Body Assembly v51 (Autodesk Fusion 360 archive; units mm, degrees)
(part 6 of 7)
sketch "Sketch1" plane through (0, 0, 0) normal (0, 0, 1) x axis (1, 0, 0)
  line L1 (-7.25, -8.75) -> (7.25, -8.75)
  line L2 (-7.25, 8.75) -> (-7.25, -8.75)
  line L3 (7.25, 8.75) -> (-7.25, 8.75)
  line L4 (7.25, -8.75) -> (7.25, 8.75)
  line L5 (-7.25, 8.75) -> (7.25, -8.75)
  line L6 (7.25, 8.75) -> (-7.25, -8.75)
  line L7 (0, 8.75) -> (0, -8.75)
  line L8 (-2.5, -2.35) -> (2.5, -2.35)
  line L9 (-2.5, 1.45) -> (-2.5, -2.35)
  line L10 (2.5, 1.45) -> (-2.5, 1.45)
  line L11 (2.5, -2.35) -> (2.5, 1.45)
  line L12 (-2.5, 1.45) -> (2.5, -2.35)
  line L13 (2.5, 1.45) -> (-2.5, -2.35)
  line L14 (7.25, -0.45) -> (-7.25, -0.45)
  line L15 (3.75, -8.75) -> (7.25, -5.25)
  line L16 (-3.75, -8.75) -> (-7.25, -5.25)
  arc A1 centre (0, 0.1797) radius 8.5703 clockwise from (-7.25, 4.75) to (7.25, 4.75)
  circle C1 centre (6, -0.45) radius 1.5
  circle C2 centre (-6, -0.45) radius 1.5
  point P6 (0, 0)
  point P1 (0, 0)
  point P7 (0, -8.75)
  point P8 (0, 8.75)
  point P13 (0, -0.45)
  point P14 (-7.25, -0.45)
  point P15 (7.25, -0.45)
  point P16 (7.25, 4.75)
  point P17 (-7.25, 4.75)
  point P19 (7.25, 4.75)
  point P18 (-7.25, 4.75)
  point P21 (7.25, -5.25)
  point P22 (3.75, -8.75)
  point P23 (7.25, -5.25)
  point P24 (3.75, -8.75)
  point P25 (-7.25, -5.25)
  point P26 (-3.75, -8.75)
  point P27 (6, -0.45)
  point P2 (7.25, -8.75)
  point P5 (7.25, 8.75)
  horizontal L1
  perpendicular L1 L2
  parallel L1 L3
  parallel L2 L4
  coincident L5 P6
  coincident L6 P6
  coincident P1 P6
  midpoint L1 P7
  midpoint L3 P8
  horizontal L8
  perpendicular L8 L9
  parallel L8 L10
  parallel L9 L11
  coincident L12 P13
  coincident L13 P13
  coincident L7 P13
  coincident L2 P14
  coincident L4 P15
  perpendicular L4 L14
  coincident P13 L14
  coincident L4 P16
  symmetric L7 P16 P17
  coincident P8 A1
  tangent L3 A1
  coincident P16 P19
  coincident P17 P18
  coincident L4 P21
  coincident L1 P22
  coincident P21 P23
  coincident P22 P24
  symmetric L7 P23 P25
  symmetric L7 P24 P26
  coincident L14 P27
  symmetric L7 C1 C2
  dimension "d1_1" distance P2 P5 = 17.5
  dimension "d2_1" distance L2 L4 = 14.5
  dimension "d3_1" distance L1 L8 = 6.4
  dimension "d4_1" distance L3 L10 = 7.3
  dimension "d5_1" distance L9 L11 = 5
  dimension "d6_1" distance P5 P16 = 4
  dimension "d7_1" distance P2 P21 = 3.5
  dimension "d8_1" distance P2 P22 = 3.5
  dimension "d9_1" diameter C1 = 3
  dimension "d10_1" distance L11 P27 = 3.5 (= "2 mm + 1.5 mm")
extrude "Extrude1" new body sketch "Sketch1" profile of L1 L2 L4 L8 L9 L10 L11 A1 L15 L16 C1 C2 against normal blind 1.7 named "d11_1"
extrude "Extrude2" new body sketch "Sketch1" profile of L8 L9 L10 L11 along normal blind 1.5 named "d13_1"
position "Position1"
position "Position2"
position "Position3"
position "Position4"
copy_paste "CutPaste2"
work_plane "WorkPlane1" AlongDistance -21
split "Split1"
combine "Combine1"
split "Split1"
remove_body "RemoveBody2"
extrude "Extrude1" add of existing geometry blind 2.2
extrude "Extrude2" add of existing geometry blind 1
extrude "Extrude3" cut of existing geometry blind -0.2
extrude "Extrude4" add of existing geometry blind 0.2
work_plane "WorkPlane2"
extrude "Extrude4" cut of existing geometry blind -0.2063 (= "( 2 mm - ( ( 1 / 16 ) * 1 in ) ) / -2")
extrude "Extrude5" cut of existing geometry blind -0.2063 (= "( 2 mm - ( ( 1 / 16 ) * 1 in ) ) / -2")
extrude "Extrude5" add of existing geometry blind 0.2063 (= "( 2 mm - ( ( 1 / 16 ) * 1 in ) ) / 2")
extrude "Extrude6" add of existing geometry blind 0.2063 (= "( 2 mm - ( ( 1 / 16 ) * 1 in ) ) / 2")
sketch "Sketch4" plane through (0, 0, 28) normal (0, 0, -1) x axis (1, 0, 0)
  line L1 (-1.6037, -23.3708) -> (-1.6037, 14.6292)
  line L2 (-0.9037, -30.2208) -> (-0.9037, -24.3248)
  line L3 (2.4963, -31.7208) -> (0.5963, -31.7208)
  line L4 (2.4963, -31.0175) -> (2.4963, -31.7208)
  line L5 (4.4963, -31.7208) -> (4.4963, -31.0175)
  line L6 (12.2963, -31.7208) -> (4.4963, -31.7208)
  line L7 (12.2963, -31.0175) -> (12.2963, -31.7208)
  line L8 (14.2963, -31.7208) -> (14.2963, -31.0175)
  line L9 (16.1963, -31.7208) -> (14.2963, -31.7208)
  line L10 (17.6963, -24.3248) -> (17.6963, -30.2208)
  line L11 (18.3963, 14.6292) -> (18.3963, -23.3708)
  line L12 (17.6963, 21.4792) -> (17.6963, 15.5831)
  line L13 (14.2963, 22.9792) -> (16.1963, 22.9792)
  line L14 (14.2963, 22.2758) -> (14.2963, 22.9792)
  line L15 (12.2963, 22.9792) -> (12.2963, 22.2758)
  line L16 (4.4963, 22.9792) -> (12.2963, 22.9792)
  line L17 (4.4963, 22.2758) -> (4.4963, 22.9792)
  line L18 (2.4963, 22.9792) -> (2.4963, 22.2758)
  line L19 (0.5963, 22.9792) -> (2.4963, 22.9792)
  line L20 (-0.9037, 15.5831) -> (-0.9037, 21.4792)
  line L21 (15.3963, 15.6292) -> (1.3963, 15.6292)
  line L22 (1.3963, 15.6292) -> (15.3963, 15.6292)
  line L23 (8.3963, -2.0612) -> (8.3963, 15.6292)
  line L24 (22.9806, 14.6292) -> (-3.2785, 14.6292)
  arc A1 centre (-0.6037, 14.6292) radius 1 clockwise from (-1.6037, 14.6292) to (-0.9037, 15.5831)
  arc A2 centre (-0.6037, -23.3708) radius 1 clockwise from (-0.9037, -24.3248) to (-1.6037, -23.3708)
  arc A3 centre (0.5963, -30.2208) radius 1.5 clockwise from (0.5963, -31.7208) to (-0.9037, -30.2208)
  arc A4 centre (3.4963, -29.1708) radius 2.1 clockwise from (2.4963, -31.0175) to (4.4963, -31.0175)
  arc A5 centre (13.2963, -29.1708) radius 2.1 clockwise from (12.2963, -31.0175) to (14.2963, -31.0175)
  arc A6 centre (16.1963, -30.2208) radius 1.5 clockwise from (17.6963, -30.2208) to (16.1963, -31.7208)
  arc A7 centre (17.3963, -23.3708) radius 1 clockwise from (18.3963, -23.3708) to (17.6963, -24.3248)
  arc A8 centre (17.3963, 14.6292) radius 1 clockwise from (17.6963, 15.5831) to (18.3963, 14.6292)
  arc A9 centre (16.1963, 21.4792) radius 1.5 clockwise from (16.1963, 22.9792) to (17.6963, 21.4792)
  arc A10 centre (13.2963, 20.4292) radius 2.1 clockwise from (14.2963, 22.2758) to (12.2963, 22.2758)
  arc A11 centre (3.4963, 20.4292) radius 2.1 clockwise from (4.4963, 22.2758) to (2.4963, 22.2758)
  arc A12 centre (0.5963, 21.4792) radius 1.5 clockwise from (-0.9037, 21.4792) to (0.5963, 22.9792)
  circle C1 centre (8.3963, 6.1292) radius 8.5
  point P48 (8.3963, 15.6292)
  point P50 (8.3963, 6.1292)
  midpoint L21 P48
  perpendicular L21 L23
  coincident L23 P50
  perpendicular L1 L24
  tangent C1 L24
  dimension "d32" diameter C1 = 17
  dimension "d33" distance L22 L24 = 1
extrude "Extrude4" new body sketch "Sketch4" profile of C1 along normal blind 27.9908
extrude "Extrude5" add of existing geometry blind 0.5092 (= "41.5 mm - 1.6138110236220502 in")
copy_paste_bodies "CutPasteBodies1"
sketch "Sketch5" plane through (0, 0, 28) normal (0, 0, -1) x axis (1, 0, 0)
  line L1 (-1.6037, -23.3708) -> (-1.6037, 14.6292)
  line L2 (-0.9037, -30.2208) -> (-0.9037, -24.3248)
  line L3 (2.4963, -31.7208) -> (0.5963, -31.7208)
  line L4 (2.4963, -31.0175) -> (2.4963, -31.7208)
  line L5 (4.4963, -31.7208) -> (4.4963, -31.0175)
  line L6 (12.2963, -31.7208) -> (4.4963, -31.7208)
  line L7 (12.2963, -31.0175) -> (12.2963, -31.7208)
  line L8 (14.2963, -31.7208) -> (14.2963, -31.0175)
  line L9 (16.1963, -31.7208) -> (14.2963, -31.7208)
  line L10 (17.6963, -24.3248) -> (17.6963, -30.2208)
  line L11 (18.3963, 14.6292) -> (18.3963, -23.3708)
  line L12 (17.6963, 21.4792) -> (17.6963, 15.5831)
  line L13 (14.2963, 22.9792) -> (16.1963, 22.9792)
  line L14 (14.2963, 22.2758) -> (14.2963, 22.9792)
  line L15 (12.2963, 22.9792) -> (12.2963, 22.2758)
  line L16 (4.4963, 22.9792) -> (12.2963, 22.9792)
  line L17 (4.4963, 22.2758) -> (4.4963, 22.9792)
  line L18 (2.4963, 22.9792) -> (2.4963, 22.2758)
  line L19 (0.5963, 22.9792) -> (2.4963, 22.9792)
  line L20 (-0.9037, 15.5831) -> (-0.9037, 21.4792)
  arc A1 centre (-0.6037, 14.6292) radius 1 clockwise from (-1.6037, 14.6292) to (-0.9037, 15.5831)
  arc A2 centre (-0.6037, -23.3708) radius 1 clockwise from (-0.9037, -24.3248) to (-1.6037, -23.3708)
  arc A3 centre (0.5963, -30.2208) radius 1.5 clockwise from (0.5963, -31.7208) to (-0.9037, -30.2208)
  arc A4 centre (3.4963, -29.1708) radius 2.1 clockwise from (2.4963, -31.0175) to (4.4963, -31.0175)
  arc A5 centre (13.2963, -29.1708) radius 2.1 clockwise from (12.2963, -31.0175) to (14.2963, -31.0175)
  arc A6 centre (16.1963, -30.2208) radius 1.5 clockwise from (17.6963, -30.2208) to (16.1963, -31.7208)
  arc A7 centre (17.3963, -23.3708) radius 1 clockwise from (18.3963, -23.3708) to (17.6963, -24.3248)
  arc A8 centre (17.3963, 14.6292) radius 1 clockwise from (17.6963, 15.5831) to (18.3963, 14.6292)
  arc A9 centre (16.1963, 21.4792) radius 1.5 clockwise from (16.1963, 22.9792) to (17.6963, 21.4792)
  arc A10 centre (13.2963, 20.4292) radius 2.1 clockwise from (14.2963, 22.2758) to (12.2963, 22.2758)
  arc A11 centre (3.4963, 20.4292) radius 2.1 clockwise from (4.4963, 22.2758) to (2.4963, 22.2758)
  arc A12 centre (0.5963, 21.4792) radius 1.5 clockwise from (-0.9037, 21.4792) to (0.5963, 22.9792)
split "Split1"
remove_body "RemoveBody1"
delete_face "DeleteFace1"
delete_face "DeleteFace2"
sketch "Sketch6" plane through (0, 0, 28) normal (0, 0, -1) x axis (1, 0, 0)
  line L1 (-0.9037, -24.3248) -> (17.6963, 15.5831)
  line L2 (-0.9037, 15.5831) -> (17.6963, -24.3248)
  line L3 (-0.8337, -23.6158) -> (17.6263, -23.6158)
  line L4 (-0.8337, 14.8742) -> (-0.8337, -23.6158)
  line L5 (17.6263, 14.8742) -> (-0.8337, 14.8742)
  line L6 (17.6263, -23.6158) -> (17.6263, 14.8742)
  line L7 (-0.8337, 14.8742) -> (17.6263, -23.6158)
  line L8 (17.6263, 14.8742) -> (-0.8337, -23.6158)
  line L9 (-4.0087, 18.0492) -> (-4.0087, -26.7908)
  line L10 (20.8013, 18.0492) -> (-4.0087, 18.0492)
  line L11 (20.8013, -26.7908) -> (20.8013, 18.0492)
  line L12 (-4.0087, -26.7908) -> (20.8013, -26.7908)
  point P2 (17.6963, 15.5831)
  point P6 (17.6963, 15.5831)
  point P4 (-0.9037, -24.3248)
  point P7 (-0.9037, -24.3248)
  point P3 (17.6963, -24.3248)
  point P8 (17.6963, -24.3248)
  point P5 (-0.9037, 15.5831)
  point P9 (-0.9037, 15.5831)
  point P10 (8.3963, -4.3708)
  point P15 (8.3963, -4.3708)
  point P13 (-0.8337, 14.8742)
  point P14 (17.6263, 14.8742)
  point P11 (17.6263, -23.6158)
  coincident P2 P6
  coincident P4 P7
  coincident P3 P8
  coincident P5 P9
  midpoint L1 P10
  horizontal L3
  perpendicular L3 L4
  parallel L3 L5
  parallel L4 L6
  coincident L7 P15
  coincident L8 P15
  coincident P10 P15
  dimension "d38" distance P13 P14 = 18.46
  dimension "d39" distance P11 P14 = 38.49
  dimension "d44" = -3.175 (= "( -1 / 8 ) * 1 in")
split "Split2"
split "Split3"
delete_face "DeleteFace3"
extrude "Extrude1" cut of existing geometry blind -33.02
delete_face "DeleteFace4"
extrude "Extrude2" cut of existing geometry blind -29.21
extrude "Extrude6" new body sketch "Sketch6" profile of L3 L4 L5 L6 L9 L12 L10 L11 along normal blind 28.4988
work_plane "WorkPlane3" AlongDistance -1.6
split "Split2"
sketch "Sketch7" plane through (0, 0, 26.4) normal (0, 0, 1) x axis (-1, 0, 0)
  line L1 (0.8337, -23.6158) -> (0.8337, 14.8742)
  line L2 (-17.6263, -23.6158) -> (0.8337, -23.6158)
  line L3 (-17.6263, 14.8742) -> (-17.6263, -23.6158)
  line L4 (0.8337, 14.8742) -> (-17.6263, 14.8742)
  line L5 (4.0087, -26.7908) -> (-20.8013, -26.7908)
  line L6 (4.0087, 18.0492) -> (4.0087, -26.7908)
  line L7 (-20.8013, 18.0492) -> (4.0087, 18.0492)
  line L8 (-20.8013, -26.7908) -> (-20.8013, 18.0492)
  line L9 (-20.8013, 6.1292) -> (4.0087, 6.1292)
  line L10 (-20.8013, -1.8708) -> (4.0087, -1.8708)
  circle C1 centre (-8.3963, 6.1292) radius 8.5
  circle C2 centre (-8.3963, 6.1292) radius 8.75
  point P12 (4.0087, 6.1292)
  point P13 (-20.8013, 6.1292)
  point P14 (4.0087, -1.8708)
  point P15 (-20.8013, -1.8708)
  coincident L6 P12
  coincident L8 P13
  perpendicular L8 L9
  coincident L6 P14
  coincident L8 P15
  perpendicular L8 L10
  dimension "d48" = 0.25
  dimension "d51" distance L9 L10 = 8
extrude "Extrude7" add sketch "Sketch7" profile of L1 L3 L4 C2 L10 against normal blind 26.8988
extrude "Extrude8" cut sketch "Sketch7" profile of L4 C2 against normal blind 38.1
offset_faces "OffsetFaces1" distance 0.75
fillet "Fillet3" radius 1.651
split "Split3"
remove_body "RemoveBody5"
mirror "Mirror1" mirrorStitchTolerance 0.1016
combine "Combine2"
component_from_bodies "Body->Comp1"
copy_paste_bodies "CutPasteBodies1"
mirror "Mirror1" mirrorStitchTolerance 0.1016
align "Align1"
extrude "Extrude1" add of existing geometry blind 6.35
extrude "Extrude9" new body of existing geometry blind 19.9898
copy_paste_bodies "CutPasteBodies2"
copy_paste "CutPaste3"
copy_paste_bodies "CutPasteBodies2"
sketch "Sketch8" plane through (0, 0, 19.9956) normal (0, 0, -1) x axis (1, 0, 0)
  line L1 (0.3963, -22.3708) -> (0.3963, -3.3708)
  line L2 (16.3963, -22.3708) -> (0.3963, -22.3708)
  line L3 (16.3963, -3.3708) -> (16.3963, -22.3708)
  line L4 (0.3963, -3.3708) -> (16.3963, -3.3708)
  line L5 (1.5713, -6.5458) -> (1.5713, -21.1958)
  line L6 (15.2213, -6.5458) -> (1.5713, -6.5458)
  line L7 (15.2213, -21.1958) -> (15.2213, -6.5458)
  line L8 (1.5713, -21.1958) -> (15.2213, -21.1958)
  line L9 (-4.0087, 18.0492) -> (20.8013, 18.0492)
  line L10 (-4.0087, -26.7908) -> (-4.0087, 18.0492)
  line L11 (20.8013, -26.7908) -> (-4.0087, -26.7908)
  line L12 (20.8013, 18.0492) -> (20.8013, -26.7908)
  line L13 (16.8763, -22.8658) -> (16.8763, -3.2059)
  line L14 (-0.0837, -22.8658) -> (16.8763, -22.8658)
  line L15 (-0.0837, -3.2059) -> (-0.0837, -22.8658)
  circle C1 centre (8.3963, -14.6208) radius 8
  circle C2 centre (8.3963, -14.6208) radius 8
  arc A1 centre (8.3963, 6.1292) radius 8.75 clockwise from (1.4656, 0.788) to (15.327, 0.788)
  arc A2 centre (16.6347, -0.2198) radius 1.651 clockwise from (15.93, -1.7129) to (15.327, 0.788)
  arc A3 centre (15.2253, -3.2059) radius 1.651 clockwise from (15.93, -1.7129) to (16.8763, -3.2059)
  arc A4 centre (1.5673, -3.2059) radius 1.651 clockwise from (-0.0837, -3.2059) to (0.8626, -1.7129)
  arc A5 centre (0.1579, -0.2198) radius 1.651 clockwise from (1.4656, 0.788) to (0.8626, -1.7129)
  circle C3 centre (8.3963, 6.1292) radius 8.5
  circle C4 centre (8.3963, 6.1292) radius 8.75
  dimension "d72" = 0.25
extrude "Extrude10" new body sketch "Sketch8" profile of L1 L2 L3 L4 L5 L6 L7 L8 C1 C2 A2 A3 L13 L14 L15 A4 A5 C4 along normal blind 5.0038
sketch "Sketch9" plane through (0, 0, 14.9918) normal (0, 0, -1) x axis (1, 0, 0)
  line L1 (-0.0837, -22.8658) -> (-0.0837, -3.2059)
  line L2 (16.8763, -22.8658) -> (-0.0837, -22.8658)
  line L3 (16.8763, -3.2059) -> (16.8763, -22.8658)
  circle C1 centre (8.3963, -14.6208) radius 8
  arc A1 centre (15.2253, -3.2059) radius 1.651 clockwise from (15.93, -1.7129) to (16.8763, -3.2059)
  arc A2 centre (16.6347, -0.2198) radius 1.651 clockwise from (15.93, -1.7129) to (15.327, 0.788)
  arc A3 centre (8.3963, 6.1292) radius 8.75 clockwise from (15.327, 0.788) to (1.4656, 0.788)
  arc A4 centre (0.1579, -0.2198) radius 1.651 clockwise from (1.4656, 0.788) to (0.8626, -1.7129)
  arc A5 centre (1.5673, -3.2059) radius 1.651 clockwise from (-0.0837, -3.2059) to (0.8626, -1.7129)
  arc A6 centre (8.3963, 6.1292) radius 8.75 clockwise from (15.327, 0.788) to (1.4656, 0.788)
  arc A7 centre (8.3963, 6.1292) radius 11.1625 clockwise from (17.2379, -0.6847) to (-0.4452, -0.6847)
  dimension "d73" = 2.4125 (= "0.125 in - 0.0300196850393694 in")
extrude "Extrude11" add sketch "Sketch9" profile of A1 A2 A3 A4 A5 A6 A7 along normal blind 15.4906
combine "Combine3"
delete_face "DeleteFace1"
delete_face "DeleteFace2"
fillet "Fillet1" radius 4.7625
sketch "Sketch10" plane through (0, 0, 8.3168) normal (0, 0, -1) x axis (1, 0, 0)
  circle C1 centre (8.3963, -14.6208) radius 4
  circle C2 centre (8.3963, -14.6208) radius 8
  circle C3 centre (8.3963, -14.6208) radius 9.5875
  dimension "d78" = 1.5875 (= "( 1 / 16 ) * 1 in")
extrude "Extrude7" cut sketch "Sketch10" along normal blind 15.24 and against normal blind 6.6802
extrude "Extrude8" add of existing geometry blind 0.0052 (= "2.047E-04 in")
sketch "Sketch11" plane through (0, 0, 14.9918) normal (0, 0, -1) x axis (1, 0, 0)
  line L1 (16.8763, -22.8658) -> (13.2892, -22.8658)
  line L2 (16.8763, -19.0941) -> (16.8763, -22.8658)
  line L3 (16.8763, -9.3559) -> (16.8763, -10.1476)
  line L4 (-0.0837, -10.1476) -> (-0.0837, -9.3559)
  line L5 (-0.0837, -22.8658) -> (-0.0837, -19.0941)
  line L6 (3.5034, -22.8658) -> (-0.0837, -22.8658)
  circle C1 centre (8.3963, -14.6208) radius 8
  arc A1 centre (8.3963, -14.6208) radius 9.5875 clockwise from (16.8763, -10.1476) to (16.8763, -19.0941)
  arc A2 centre (12.1138, -9.3559) radius 4.7625 clockwise from (11.0021, -4.7249) to (16.8763, -9.3559)
  arc A3 centre (8.3963, 6.1292) radius 11.1625 clockwise from (11.0021, -4.7249) to (5.7906, -4.7249)
  arc A4 centre (4.6788, -9.3559) radius 4.7625 clockwise from (-0.0837, -9.3559) to (5.7906, -4.7249)
  arc A5 centre (8.3963, -14.6208) radius 9.5875 clockwise from (-0.0837, -19.0941) to (-0.0837, -10.1476)
  arc A6 centre (8.3963, -14.6208) radius 9.5875 clockwise from (13.2892, -22.8658) to (3.5034, -22.8658)
  circle C2 centre (8.3963, -14.6208) radius 9.5875
  dimension "d85" = 1.5875 (= "( 1 / 16 ) * 1 in")
extrude "Extrude9" add sketch "Sketch11" profile of L1 L2 L3 A2 A3 A4 L4 L5 L6 C2 along normal blind 15.494
extrude "Extrude10" cut of existing geometry blind -0.0034 (= "-1.339E-04 in")
extrude "Extrude3" cut of existing geometry blind -0.508
extrude "Extrude11" cut of existing geometry blind -0.508
extrude "Extrude4" cut of existing geometry blind -1
offset_faces "OffsetFaces1" distance 1.5875 (= "( 1 / 16 ) * 1 in")
split "Split2"
delete_face "DeleteFace3"
combine "Combine4"
split "Split3"
sketch "Sketch12" plane through (0, 0, 4.8168) normal (0, 0, 1) x axis (-1, 0, 0)
  line L1 (-4.6463, -6.3208) -> (-1.1463, -9.8208)
  line L2 (-12.1463, -6.3208) -> (-4.6463, -6.3208)
  line L3 (-15.6463, -9.8208) -> (-12.1463, -6.3208)
  line L4 (-15.6463, -13.7917) -> (-15.6463, -9.8208)
  line L5 (-15.6463, -19.8208) -> (-15.6463, -15.45)
  line L6 (-1.1463, -15.45) -> (-1.1463, -19.8208)
  line L7 (-1.1463, -9.8208) -> (-1.1463, -13.7917)
  line L8 (-12.1463, -6.3208) -> (-15.6463, -9.8208)
  line L9 (-4.6463, -6.3208) -> (-12.1463, -6.3208)
  line L10 (-4.6463, -6.3208) -> (-1.1463, -9.8208)
  line L11 (-15.6463, -9.8208) -> (-15.6463, -19.8208)
  line L12 (-1.1463, -9.8208) -> (-1.1463, -19.8208)
  line L13 (-0.8963, -9.7173) -> (-0.8963, -19.8925)
  line L14 (-4.5428, -6.0708) -> (-0.8963, -9.7173)
  line L15 (-4.5428, -6.0708) -> (-12.2499, -6.0708)
  line L16 (-12.2499, -6.0708) -> (-15.8963, -9.7173)
  line L17 (-15.8963, -9.7173) -> (-15.8963, -19.8925)
  arc A1 centre (-14.3963, -14.6208) radius 1.5 clockwise from (-15.6463, -13.7917) to (-15.6463, -15.45)
  arc A2 centre (-8.3963, -15.2505) radius 8.5703 clockwise from (-1.1463, -19.8208) to (-15.6463, -19.8208)
  arc A3 centre (-2.3963, -14.6208) radius 1.5 clockwise from (-1.1463, -15.45) to (-1.1463, -13.7917)
  arc A4 centre (-8.3963, -15.2505) radius 8.5703 clockwise from (-1.1463, -19.8208) to (-15.6463, -19.8208)
  arc A5 centre (-8.3963, -15.2505) radius 8.8203 clockwise from (-0.8963, -19.8925) to (-15.8963, -19.8925)
  circle C1 centre (-8.3963, -14.6208) radius 9.5875
  point P15 (-15.6463, -19.8208)
  point P22 (-15.6463, -19.8208)
  point P18 (-15.6463, -9.8208)
  point P23 (-15.6463, -9.8208)
  point P16 (-1.1463, -19.8208)
  point P24 (-1.1463, -19.8208)
  point P21 (-1.1463, -9.8208)
  point P25 (-1.1463, -9.8208)
  coincident P15 P22
  coincident P18 P23
  coincident P16 P24
  coincident P21 P25
  dimension "d97" = 0.25
extrude "Extrude12" add sketch "Sketch12" profile of A5 L13 L14 L15 L16 L17 C1 against normal blind 4.8006
extrude "Extrude13" add of existing geometry blind 0.007 (= "2.756E-04 in")
split "Split4"
delete_face "DeleteFace4"
delete_face "DeleteFace5"
combine "Combine5"
extrude "Extrude14" add of existing geometry blind 1.4986
extrude "Extrude15" add of existing geometry blind 0.0014 (= "5.512E-05 in")
sketch "Sketch13" plane through (0, 0, 6.3168) normal (0, 0, 1) x axis (-1, 0, 0)
  line L1 (-15.8963, -9.7173) -> (-15.8963, -19.8925)
  line L2 (-12.2499, -6.0708) -> (-15.8963, -9.7173)
  line L3 (-4.5428, -6.0708) -> (-12.2499, -6.0708)
  line L4 (-0.8963, -9.7173) -> (-4.5428, -6.0708)
  line L5 (-0.8963, -19.8925) -> (-0.8963, -9.7173)
  line L6 (5.5962, 19.6367) -> (5.5962, -28.3783)
  line L7 (-22.3888, 19.6367) -> (5.5962, 19.6367)
  line L8 (-22.3888, -28.3783) -> (-22.3888, 19.6367)
  line L9 (5.5962, -28.3783) -> (-22.3888, -28.3783)
  line L10 (-3.6338, -52.7208) -> (-13.1588, -52.7208)
  line L11 (-3.6338, 23.4792) -> (-3.6338, -52.7208)
  line L12 (-13.1588, 23.4792) -> (-3.6338, 23.4792)
  line L13 (-13.1588, -52.7208) -> (-13.1588, 23.4792)
  line L14 (-3.6338, 23.4792) -> (-13.1588, -52.7208)
  line L15 (-13.1588, 23.4792) -> (-3.6338, -52.7208)
  arc A1 centre (-8.3963, -15.2505) radius 8.8203 clockwise from (-0.8963, -19.8925) to (-15.8963, -19.8925)
  circle C1 centre (-8.3963, 6.1292) radius 8.75
  circle C2 centre (-8.3963, -14.6208) radius 4
  point P19 (-8.3963, -14.6208)
  point P14 (-8.3963, -14.6208)
  point P15 (-13.1588, -52.7208)
  point P16 (-3.6338, -52.7208)
  point P18 (-13.1588, 23.4792)
  horizontal L10
  perpendicular L10 L11
  parallel L10 L12
  parallel L11 L13
  coincident L14 P19
  coincident L15 P19
  coincident P14 P19
  dimension "d106" distance P15 P16 = 9.525
  dimension "d107" distance P15 P18 = 76.2
extrude "Extrude16" cut sketch "Sketch13" profile of A1 L9 L11 L13 against normal blind 3.2004
extrude "Extrude17" cut sketch "Sketch13" profile of L7 C1 L11 L13 against normal blind 5.3086
extrude "Extrude18" cut of existing geometry blind -0.0002 (= "-7.873E-06 in")
extrude "Extrude19" add of existing geometry blind 0.0004 (= "1.574E-05 in")
combine "Combine1"
offset_faces "OffsetFaces2" distance 0.7937 (= "( 1 / 32 ) * 1 in")
extrude "Extrude20" add of existing geometry blind 2.175 (= "0.125 in - 1 mm")
sketch "Sketch14" plane through (0, 0, 28) normal (0, 0, 1) x axis (-1, 0, 0)
  line L1 (0.8337, 14.8742) -> (-17.6263, 14.8742)
  line L2 (0.8337, -23.6158) -> (0.8337, 14.8742)
  line L3 (-17.6263, -23.6158) -> (0.8337, -23.6158)
  line L4 (-17.6263, 14.8742) -> (-17.6263, -23.6158)
  line L5 (-22.3888, -28.3783) -> (-22.3888, 19.6367)
  line L6 (5.5962, -28.3783) -> (-22.3888, -28.3783)
  line L7 (5.5962, 19.6367) -> (5.5962, -28.3783)
  line L8 (-22.3888, 19.6367) -> (5.5962, 19.6367)
  line L9 (-17.6963, 15.5831) -> (0.9037, 15.5831)
  line L10 (0.9037, 15.5831) -> (-17.6963, 15.5831)
  line L11 (-18.3963, -23.3708) -> (-18.3963, 14.6292)
  line L12 (-18.3963, -17.3601) -> (-18.3963, -23.3708)
  line L13 (-18.3963, -4.3708) -> (-18.3963, -17.3601)
  line L14 (-18.3963, 14.6292) -> (-18.3963, -4.3708)
  line L15 (1.6037, 14.6292) -> (1.6037, -23.3708)
  line L16 (1.6037, -4.3708) -> (1.6037, 14.6292)
  line L17 (1.6037, -17.3601) -> (1.6037, -4.3708)
  line L18 (1.6037, -23.3708) -> (1.6037, -17.3601)
  line L19 (-17.6963, -24.3248) -> (0.9037, -24.3248)
  line L20 (0.9037, -24.3248) -> (-17.6963, -24.3248)
  arc A1 centre (-17.3963, 14.6292) radius 1 clockwise from (-18.3963, 14.6292) to (-17.6963, 15.5831)
  arc A2 centre (-17.3963, 14.6292) radius 1 clockwise from (-18.3963, 14.6292) to (-17.6963, 15.5831)
  arc A3 centre (0.6037, 14.6292) radius 1 clockwise from (0.9037, 15.5831) to (1.6037, 14.6292)
  arc A4 centre (0.6037, 14.6292) radius 1 clockwise from (0.9037, 15.5831) to (1.6037, 14.6292)
  arc A5 centre (0.6037, -23.3708) radius 1 clockwise from (1.6037, -23.3708) to (0.9037, -24.3248)
  arc A6 centre (0.6037, -23.3708) radius 1 clockwise from (1.6037, -23.3708) to (0.9037, -24.3248)
  arc A7 centre (-17.3963, -23.3708) radius 1 clockwise from (-17.6963, -24.3248) to (-18.3963, -23.3708)
  arc A8 centre (-17.3963, -23.3708) radius 1 clockwise from (-17.6963, -24.3248) to (-18.3963, -23.3708)
extrude "Extrude21" add sketch "Sketch14" profile of L5 L6 L7 L8 A1 A2 L9 L10 L11 L12 L13 L14 A3 A4 L15 L16 L17 L18 A5 A6 L19 L20 A7 A8 along normal blind 13.0048
split "Split5"
extrude "Extrude22" add of existing geometry blind 2
remove_body "RemoveBody3"
copy_paste "CutPaste1"
copy_paste_bodies "CutPasteBodies1"
remove_instance "RemoveInstance2"
split "Split6"
remove_body "RemoveBody4"
combine "Combine1"
offset_faces "OffsetFaces3" distance 4.93 (= "0.1315944881889787 in + ( 1 / 16 ) * 1 in")
sketch "Sketch16" plane through (0, 0, 28) normal (0, 0, 1) x axis (-1, 0, 0)
  line L1 (5.5962, 24.5667) -> (5.5962, -33.3083)
  line L2 (-22.3888, 24.5667) -> (5.5962, 24.5667)
  line L3 (-22.3888, -33.3083) -> (-22.3888, 24.5667)
  line L4 (5.5962, -33.3083) -> (-22.3888, -33.3083)
  line L5 (0.8337, 14.8742) -> (-17.6263, 14.8742)
  line L6 (0.8337, -23.6158) -> (0.8337, 14.8742)
  line L7 (-17.6263, -23.6158) -> (0.8337, -23.6158)
  line L8 (-17.6263, 14.8742) -> (-17.6263, -23.6158)
  arc A1 centre (-3.4963, 20.4292) radius 2.1 clockwise from (-2.4963, 22.2758) to (-4.4963, 22.2758)
  circle C1 centre (-3.4963, 20.4292) radius 1.5
  concentric A1 C1
  dimension "d141" diameter C1 = 3
work_plane "WorkPlane5"
chamfer "Chamfer1" distance 6.35
split "Split7"
sketch "Sketch17" plane through (0, 0, 28) normal (0, 0, 1) x axis (-1, 0, 0)
  line L1 (0.8337, 14.8742) -> (-17.6263, 14.8742)
  line L2 (0.8337, -23.6158) -> (0.8337, 14.8742)
  line L3 (-17.6263, -23.6158) -> (0.8337, -23.6158)
  line L4 (-17.6263, 14.8742) -> (-17.6263, -23.6158)
  line L5 (5.5962, -26.9583) -> (-0.7538, -33.3083)
  line L6 (5.5962, 18.2167) -> (5.5962, -26.9583)
  line L7 (-0.7538, 24.5667) -> (5.5962, 18.2167)
  line L8 (-16.0388, 24.5667) -> (-0.7538, 24.5667)
  line L9 (-22.3888, 18.2167) -> (-16.0388, 24.5667)
  line L10 (-22.3888, -26.9583) -> (-22.3888, 18.2167)
  line L11 (-16.0388, -33.3083) -> (-22.3888, -26.9583)
  line L12 (-0.7538, -33.3083) -> (-16.0388, -33.3083)
  arc A1 centre (-3.4963, 20.4292) radius 2.1 clockwise from (-2.4963, 22.2758) to (-4.4963, 22.2758)
  circle C1 centre (-3.4963, 20.4292) radius 2.2
  concentric A1 C1
  dimension "d149" diameter C1 = 4.4
extrude "Extrude26" cut sketch "Sketch17" profile of C1 against normal blind 6
mirror "Mirror4" mirrorStitchTolerance 0.1016
mirror "Mirror5" mirrorStitchTolerance 0.1016
sketch "Sketch1" plane through (0, 0, 0) normal (0, 0, 1) x axis (1, 0, 0)
  circle C1 centre (0, 0) radius 2.45
  circle C2 centre (0, 0) radius 1.5
  circle C3 centre (0, 0) radius 1.95
  point P1 (0, 0)
  point P2 (0, 0)
  coincident P1 P2
  concentric C1 C2
  concentric C1 C3
  dimension "d1_2" diameter C1 = 4.9
  dimension "d2_2" diameter C2 = 3
  dimension "d3_2" diameter C3 = 3.9
extrude "Extrude1" new body sketch "Sketch1" distance 0.7 (= "( 1.4 / 2 ) * 1 mm") named "d4_2"
extrude "Extrude2" add sketch "Sketch1" profile of C2 C3 distance 3.3 (= "5 mm - 1.7 mm") named "d6_2"
extrude "Extrude3" of existing geometry blind 1.7 named "d9_2"
extrude "Extrude4" add of existing geometry blind 1.7 named "d11_2"
mirror "Mirror1" mirrorStitchTolerance 0.1 named "d14_1"
extrude "Extrude5" new body sketch "Sketch1" profile of C2 C3 distance 3 named "d15_1"
extrude "Extrude6" sketch "Sketch1" blind -1.8 named "d18_1"
mirror "Mirror2" mirrorStitchTolerance 0.1 named "d21_1"
move "Move1"
copy_paste "CutPaste4"
remove_body "RemoveBody1"
align "Align1"
mirror "Mirror3" mirrorStitchTolerance 0.1016
mirror "Mirror4" mirrorStitchTolerance 0.1016
base_feature "Base Feature1"
base_feature "Base Feature1"
base_feature "Base Feature1"
base_feature "Base Feature1"
base_feature "Base Feature1"
base_feature "Base Feature1"
copy_paste "CutPaste5"
remove_instance "RemoveInstance4"
align "Align1"
mirror "Mirror1" mirrorStitchTolerance 0.1016
mirror "Mirror2" mirrorStitchTolerance 0.1016
sketch "Sketch18" plane through (0, 0, -2.1658) normal (0, 0, -1) x axis (1, 0, 0)
  line L1 (0.7538, -33.3083) -> (-5.5962, -26.9583)
  line L2 (16.0388, -33.3083) -> (0.7538, -33.3083)
  line L3 (22.3888, -26.9583) -> (16.0388, -33.3083)
  line L4 (22.3888, 18.2167) -> (22.3888, -26.9583)
  line L5 (16.0388, 24.5667) -> (22.3888, 18.2167)
  line L6 (0.7538, 24.5667) -> (16.0388, 24.5667)
  line L7 (-5.5962, 18.2167) -> (0.7538, 24.5667)
  line L8 (-5.5962, -26.9583) -> (-5.5962, 18.2167)
  line L9 (-5.5962, -26.9583) -> (0.7538, -33.3083)
  line L10 (-5.5962, 18.2167) -> (-5.5962, -26.9583)
  line L11 (0.7538, 24.5667) -> (-5.5962, 18.2167)
  line L12 (3.6338, 24.5667) -> (0.7538, 24.5667)
  line L13 (3.6338, 13.4695) -> (3.6338, 24.5667)
  line L14 (13.1588, 24.5667) -> (13.1588, 13.4695)
  line L15 (16.0388, 24.5667) -> (13.1588, 24.5667)
  line L16 (22.3888, 18.2167) -> (16.0388, 24.5667)
  line L17 (22.3888, -26.9583) -> (22.3888, 18.2167)
  line L18 (16.0388, -33.3083) -> (22.3888, -26.9583)
  line L19 (13.1588, -33.3083) -> (16.0388, -33.3083)
  line L20 (13.1588, -22.6746) -> (13.1588, -33.3083)
  line L21 (15.8963, -9.7173) -> (15.8963, -19.8925)
  line L22 (12.2499, -6.0708) -> (15.8963, -9.7173)
  line L23 (4.5428, -6.0708) -> (12.2499, -6.0708)
  line L24 (0.8963, -9.7173) -> (4.5428, -6.0708)
  line L25 (0.8963, -19.8925) -> (0.8963, -9.7173)
  line L26 (3.6338, -33.3083) -> (3.6338, -22.6746)
  line L27 (0.7538, -33.3083) -> (3.6338, -33.3083)
  line L28 (-5.5962, -26.9583) -> (22.3888, 18.2167)
  line L29 (-5.5962, 18.2167) -> (22.3888, -26.9583)
  line L30 (-1.1287, -25.0083) -> (17.9213, -25.0083)
  line L31 (-1.1287, 16.2667) -> (-1.1287, -25.0083)
  line L32 (17.9213, 16.2667) -> (-1.1287, 16.2667)
  line L33 (17.9213, -25.0083) -> (17.9213, 16.2667)
  line L34 (-1.1287, 16.2667) -> (17.9213, -25.0083)
  line L35 (17.9213, 16.2667) -> (-1.1287, -25.0083)
  arc A1 centre (8.3963, 6.1292) radius 8.75 clockwise from (13.1588, 13.4695) to (3.6338, 13.4695)
  arc A2 centre (8.3963, -15.2505) radius 8.8203 clockwise from (15.8963, -19.8925) to (13.1588, -22.6746)
  arc A3 centre (8.3963, -15.2505) radius 8.8203 clockwise from (3.6338, -22.6746) to (0.8963, -19.8925)
  circle C1 centre (17.9213, 16.2667) radius 2.2
  point P20 (22.3888, 18.2167)
  point P34 (22.3888, 18.2167)
  point P11 (-5.5962, -26.9583)
  point P35 (-5.5962, -26.9583)
  point P21 (22.3888, -26.9583)
  point P36 (22.3888, -26.9583)
  point P12 (-5.5962, 18.2167)
  point P37 (-5.5962, 18.2167)
  point P38 (8.3963, -4.3708)
  point P43 (8.3963, -4.3708)
  point P42 (17.9213, 16.2667)
  point P44 (17.9213, 16.2667)
  point P39 (17.9213, -25.0083)
  point P41 (-1.1287, 16.2667)
  coincident P20 P34
  coincident P11 P35
  coincident P21 P36
  coincident P12 P37
  midpoint L29 P38
  horizontal L30
  perpendicular L30 L31
  parallel L30 L32
  parallel L31 L33
  coincident L34 P43
  coincident L35 P43
  coincident P38 P43
  coincident P42 P44
  dimension "d164" distance P39 P42 = 41.275
  dimension "d165" distance P41 P42 = 19.05
  dimension "d166" diameter C1 = 4.4
extrude "Extrude27" cut sketch "Sketch18" profile of C1 against normal blind 6
mirror "Mirror6" mirrorStitchTolerance 0.1016
mirror "Mirror7" mirrorStitchTolerance 0.1016
copy_paste_bodies "CopyPasteBodies1"
move "Move2"
align "Align2"
mirror "Mirror5" mirrorStitchTolerance 0.1016
mirror "Mirror6" mirrorStitchTolerance 0.1016
offset_faces "OffsetFaces4" distance 0.7937 (= "( 1 / 32 ) * 1 in")
delete_face "DeleteFace8"
delete_face "DeleteFace9"
delete_face "DeleteFace10"
delete_face "DeleteFace11"
delete_face "DeleteFace12"
delete_face "DeleteFace13"
delete_face "DeleteFace14"
delete_face "DeleteFace15"
chamfer "Chamfer2" distance 6.35
sketch "Sketch19" plane through (0, 0, 8.3168) normal (0, 0, 1) x axis (-1, 0, 0)
  line L1 (-16.8326, -34.1021) -> (-23.1826, -27.7521)
  line L2 (-13.1588, -34.1021) -> (-16.8326, -34.1021)
  line L3 (-13.1588, -22.6746) -> (-13.1588, -34.1021)
  line L4 (-15.8963, -9.7173) -> (-15.8963, -19.8925)
  line L5 (-12.2499, -6.0708) -> (-15.8963, -9.7173)
  line L6 (-4.5428, -6.0708) -> (-12.2499, -6.0708)
  line L7 (-0.8963, -9.7173) -> (-4.5428, -6.0708)
  line L8 (-0.8963, -19.8925) -> (-0.8963, -9.7173)
  line L9 (-3.6338, -34.1021) -> (-3.6338, -22.6746)
  line L10 (0.0399, -34.1021) -> (-3.6338, -34.1021)
  line L11 (6.3899, -27.7521) -> (0.0399, -34.1021)
  line L12 (6.3899, 19.0104) -> (6.3899, -27.7521)
  line L13 (0.0399, 25.3604) -> (6.3899, 19.0104)
  line L14 (-3.6338, 25.3604) -> (0.0399, 25.3604)
  line L15 (-3.6338, 13.4695) -> (-3.6338, 25.3604)
  line L16 (-13.1588, 25.3604) -> (-13.1588, 13.4695)
  line L17 (-16.8326, 25.3604) -> (-13.1588, 25.3604)
  line L18 (-23.1826, 19.0104) -> (-16.8326, 25.3604)
  line L19 (-23.1826, -27.7521) -> (-23.1826, 19.0104)
  line L20 (-14.7463, -14.6208) -> (-2.0463, -14.6208)
  arc A1 centre (-8.3963, -15.2505) radius 8.8203 clockwise from (-13.1588, -22.6746) to (-15.8963, -19.8925)
  arc A2 centre (-8.3963, -15.2505) radius 8.8203 clockwise from (-0.8963, -19.8925) to (-3.6338, -22.6746)
  arc A3 centre (-8.3963, 6.1292) radius 8.75 clockwise from (-3.6338, 13.4695) to (-13.1588, 13.4695)
  circle C1 centre (-8.3963, -14.6208) radius 4
  arc A4 centre (-7.6763, -14.8049) radius 9.6671 clockwise from (-15.8963, -19.8925) to (-15.8963, -9.7173)
  arc A5 centre (-9.1163, -14.8049) radius 9.6671 clockwise from (-0.8963, -9.7173) to (-0.8963, -19.8925)
  point P26 (-8.3963, -14.6208)
  point P29 (-8.3963, -14.6208)
  point P6 (-15.8963, -19.8925)
  point P31 (-15.8963, -19.8925)
  point P8 (-15.8963, -9.7173)
  point P30 (-15.8963, -9.7173)
  point P11 (-0.8963, -9.7173)
  point P34 (-0.8963, -9.7173)
  point P12 (-0.8963, -19.8925)
  point P33 (-0.8963, -19.8925)
  point P27 (-2.0463, -14.6208)
  point P28 (-14.7463, -14.6208)
  perpendicular L4 L20
  coincident P26 P29
  midpoint L20 P29
  coincident P6 P31
  coincident P8 P30
  coincident P11 P34
  coincident P12 P33
  tangent A1 A4
  tangent A2 A5
  dimension "d179" distance P27 P28 = 12.7
extrude "Extrude28" cut sketch "Sketch19" profile of L4 L8 A4 A5 against normal blind 2
sketch "Sketch20" plane through (0, 0, 26.4) normal (0, 0, 1) x axis (-1, 0, 0)
  line L1 (-17.6263, 14.8742) -> (-8.6921, 14.8742)
  line L2 (-17.6263, -23.6158) -> (-17.6263, 14.8742)
  line L3 (0.8337, -23.6158) -> (-17.6263, -23.6158)
  line L4 (0.8337, 14.8742) -> (0.8337, -23.6158)
  line L5 (-8.1005, 14.8742) -> (0.8337, 14.8742)
  line L6 (0.0837, -22.8658) -> (0.0837, -3.2059)
  line L7 (-16.8763, -22.8658) -> (0.0837, -22.8658)
  line L8 (-16.8763, -3.2059) -> (-16.8763, -22.8658)
  line L9 (-16.8763, 12.104) -> (-16.8763, -3.2059)
  line L10 (0.0837, 11.1729) -> (0.0837, -3.2059)
  arc A1 centre (-8.3963, 6.1292) radius 8.75 clockwise from (-8.1005, 14.8742) to (-1.4656, 0.788)
  arc A2 centre (-0.1579, -0.2198) radius 1.651 clockwise from (-0.8626, -1.7129) to (-1.4656, 0.788)
  arc A3 centre (-1.5673, -3.2059) radius 1.651 clockwise from (-0.8626, -1.7129) to (0.0837, -3.2059)
  arc A4 centre (-15.2253, -3.2059) radius 1.651 clockwise from (-16.8763, -3.2059) to (-15.93, -1.7129)
  arc A5 centre (-16.6347, -0.2198) radius 1.651 clockwise from (-15.327, 0.788) to (-15.93, -1.7129)
  arc A6 centre (-8.3963, 6.1292) radius 8.75 clockwise from (-15.327, 0.788) to (-8.6921, 14.8742)
  point P16 (-16.8763, -3.2059)
  point P21 (-16.8763, -3.2059)
  point P12 (0.0837, -3.2059)
  point P23 (0.0837, -3.2059)
  coincident P16 P21
  tangent A4 L9
  coincident P12 P23
  tangent A3 L10
extrude "Extrude29" cut sketch "Sketch20" profile of A1 A2 A3 A4 A5 A6 L9 L10 against normal blind 6.4008
extrude "Extrude30" cut of existing geometry blind -0.0036 (= "-1.417E-04 in")
component_from_bodies "Body->Comp1"
component_from_bodies "Body->Comp2"
component_from_bodies "Body->Comp3"
sketch "Sketch21" plane through (0, 0, 8.3168) normal (0, 0, 1) x axis (-1, 0, 0)
  line L1 (-3.6338, -34.1021) -> (-3.6338, -22.6746)
  line L2 (0.0399, -34.1021) -> (-3.6338, -34.1021)
  line L3 (6.3899, -27.7521) -> (0.0399, -34.1021)
  line L4 (6.3899, 19.0104) -> (6.3899, -27.7521)
  line L5 (0.0399, 25.3604) -> (6.3899, 19.0104)
  line L6 (-3.6338, 25.3604) -> (0.0399, 25.3604)
  line L7 (-3.6338, 13.4695) -> (-3.6338, 25.3604)
  line L8 (-13.1588, 25.3604) -> (-13.1588, 13.4695)
  line L9 (-16.8326, 25.3604) -> (-13.1588, 25.3604)
  line L10 (-23.1826, 19.0104) -> (-16.8326, 25.3604)
  line L11 (-23.1826, -27.7521) -> (-23.1826, 19.0104)
  line L12 (-16.8326, -34.1021) -> (-23.1826, -27.7521)
  line L13 (-13.1588, -34.1021) -> (-16.8326, -34.1021)
  line L14 (-13.1588, -22.6746) -> (-13.1588, -34.1021)
  line L15 (-12.2499, -6.0708) -> (-15.8963, -9.7173)
  line L16 (-4.5428, -6.0708) -> (-12.2499, -6.0708)
  line L17 (-0.8963, -9.7173) -> (-4.5428, -6.0708)
  line L18 (-0.8963, -9.7173) -> (-0.8963, -19.8925)
  line L19 (-4.5428, -6.0708) -> (-0.8963, -9.7173)
  line L20 (-12.2499, -6.0708) -> (-4.5428, -6.0708)
  line L21 (-15.8963, -9.7173) -> (-12.2499, -6.0708)
  line L22 (-15.8963, -19.8925) -> (-15.8963, -9.7173)
  line L23 (-13.1588, -34.1021) -> (-13.1588, -22.6746)
  line L24 (-3.6338, -34.1021) -> (-13.1588, -34.1021)
  line L25 (-3.6338, -22.6746) -> (-3.6338, -34.1021)
  arc A1 centre (-9.1163, -14.8049) radius 9.6671 clockwise from (-0.8963, -9.7173) to (-0.8963, -19.8925)
  arc A2 centre (-8.3963, -15.2505) radius 8.8203 clockwise from (-0.8963, -19.8925) to (-3.6338, -22.6746)
  arc A3 centre (-8.3963, 6.1292) radius 8.75 clockwise from (-3.6338, 13.4695) to (-13.1588, 13.4695)
  arc A4 centre (-8.3963, -15.2505) radius 8.8203 clockwise from (-13.1588, -22.6746) to (-15.8963, -19.8925)
  arc A5 centre (-7.6763, -14.8049) radius 9.6671 clockwise from (-15.8963, -19.8925) to (-15.8963, -9.7173)
  arc A6 centre (-8.3963, -15.2505) radius 8.5703 clockwise from (-1.1463, -19.8208) to (-15.6463, -19.8208)
  arc A7 centre (-8.3963, -15.2505) radius 8.8203 clockwise from (-3.6338, -22.6746) to (-13.1588, -22.6746)
  arc A8 centre (-8.3963, -15.2505) radius 8.8203 clockwise from (-13.1588, -22.6746) to (-15.8963, -19.8925)
  arc A9 centre (-8.3963, -15.2505) radius 8.8203 clockwise from (-0.8963, -19.8925) to (-3.6338, -22.6746)
  point P22 (-13.1588, -22.6746)
  point P32 (-13.1588, -22.6746)
  point P5 (-3.6338, -22.6746)
  point P31 (-3.6338, -22.6746)
  coincident P22 P32
  coincident P5 P31
  tangent A4 A7
extrude "Extrude1" add sketch "Sketch21" profile of L1 L14 A7 L23 L24 L25 against normal blind 5.207
move_face "MoveFace1"
position "Position5"
sketch "Sketch22" plane through (0, 0, 8.3168) normal (0, 0, 1) x axis (-1, 0, 0)
  line L1 (0.1537, -10.7673) -> (-3.4928, -7.1208)
  line L2 (0.1537, -18.4744) -> (0.1537, -10.7673)
  line L3 (-3.4928, -22.1208) -> (0.1537, -18.4744)
  line L4 (0.0399, -34.1021) -> (-16.8326, -34.1021)
  line L5 (6.3899, -27.7521) -> (0.0399, -34.1021)
  line L6 (6.3899, 19.0104) -> (6.3899, -27.7521)
  line L7 (0.0399, 25.3604) -> (6.3899, 19.0104)
  line L8 (-3.6338, 25.3604) -> (0.0399, 25.3604)
  line L9 (-3.6338, 13.4695) -> (-3.6338, 25.3604)
  line L10 (-13.1588, 25.3604) -> (-13.1588, 13.4695)
  line L11 (-16.8326, 25.3604) -> (-13.1588, 25.3604)
  line L12 (-23.1826, 19.0104) -> (-16.8326, 25.3604)
  line L13 (-23.1826, -27.7521) -> (-23.1826, 19.0104)
  line L14 (-16.8326, -34.1021) -> (-23.1826, -27.7521)
  line L15 (-10.2963, -17.1208) -> (-10.2963, -12.1208)
  line L16 (-6.4963, -17.1208) -> (-10.2963, -17.1208)
  line L17 (-6.4963, -12.1208) -> (-6.4963, -17.1208)
  line L18 (-10.2963, -12.1208) -> (-6.4963, -12.1208)
  line L19 (-3.6338, 25.3604) -> (-3.6338, 13.4695)
  line L20 (-13.1588, 25.3604) -> (-3.6338, 25.3604)
  line L21 (-13.1588, 13.4695) -> (-13.1588, 25.3604)
  line L22 (-6.4963, -12.1208) -> (-10.2963, -17.1208)
  line L23 (-6.4963, -17.1208) -> (-10.2963, -12.1208)
  line L24 (11.7059, -11.4458) -> (-28.4985, -11.4458)
  line L25 (11.7059, -17.7958) -> (11.7059, -11.4458)
  line L26 (-28.4985, -17.7958) -> (11.7059, -17.7958)
  line L27 (-28.4985, -11.4458) -> (-28.4985, -17.7958)
  line L28 (11.7059, -17.7958) -> (-28.4985, -11.4458)
  line L29 (-28.4985, -17.7958) -> (11.7059, -11.4458)
  line L30 (14.7067, 9.3042) -> (-31.4993, 9.3042)
  line L31 (14.7067, 2.9542) -> (14.7067, 9.3042)
  line L32 (-31.4993, 2.9542) -> (14.7067, 2.9542)
  line L33 (-31.4993, 9.3042) -> (-31.4993, 2.9542)
  line L34 (14.7067, 2.9542) -> (-31.4993, 9.3042)
  line L35 (-31.4993, 2.9542) -> (14.7067, 9.3042)
  arc A1 centre (-9.026, -14.6208) radius 8.8203 clockwise from (-13.668, -22.1208) to (-13.668, -7.1208)
  arc A2 centre (-8.5804, -15.3408) radius 9.6671 clockwise from (-13.668, -7.1208) to (-3.4928, -7.1208)
  arc A3 centre (-8.5804, -13.9008) radius 9.6671 clockwise from (-3.4928, -22.1208) to (-13.668, -22.1208)
  arc A4 centre (-8.3963, 6.1292) radius 8.75 clockwise from (-3.6338, 13.4695) to (-13.1588, 13.4695)
  arc A5 centre (-8.3963, 6.1292) radius 8.75 clockwise from (-3.6338, 13.4695) to (-13.1588, 13.4695)
  circle C1 centre (-8.3963, 6.1292) radius 8.75
  point P25 (-10.2963, -17.1208)
  point P33 (-10.2963, -17.1208)
  point P27 (-6.4963, -12.1208)
  point P34 (-6.4963, -12.1208)
  point P24 (-10.2963, -12.1208)
  point P35 (-10.2963, -12.1208)
  point P26 (-6.4963, -17.1208)
  point P36 (-6.4963, -17.1208)
  point P37 (-8.3963, -14.6208)
  point P42 (-8.3963, -14.6208)
  point P47 (-8.3963, 6.1292)
  point P30 (-8.3963, 6.1292)
  point P28 (-13.1588, 13.4695)
  point P43 (-31.4993, 9.3042)
  point P46 (-31.4993, 2.9542)
  point P38 (-28.4985, -11.4458)
  point P41 (-28.4985, -17.7958)
  coincident P25 P33
  coincident P27 P34
  coincident P24 P35
  coincident P26 P36
  midpoint L23 P37
  horizontal L24
  perpendicular L24 L25
  parallel L24 L26
  parallel L25 L27
  coincident L28 P42
  coincident L29 P42
  coincident P37 P42
  horizontal L30
  perpendicular L30 L31
  parallel L30 L32
  parallel L31 L33
  coincident L34 P47
  coincident L35 P47
  coincident P30 P47
  concentric A5 C1
  coincident P28 C1
  dimension "d189" distance P43 P46 = 6.35
  dimension "d190" distance P38 P41 = 6.35
extrude "Extrude2" add sketch "Sketch22" profile of L9 L10 L19 L20 L21 C1 against normal blind 7.3152
extrude "Extrude3" cut sketch "Sketch22" profile of A4 L13 A5 L30 L32 C1 against normal blind 7.3152
extrude "Extrude4" cut sketch "Sketch22" profile of A1 L13 L24 L26 against normal blind 5.207
extrude "Extrude5" add of existing geometry blind 0.0064 (= "2.520E-04 in")
extrude "Extrude6" add of existing geometry blind 0.007 (= "2.756E-04 in")
sketch "Sketch23" plane through (0, 0, 8.3168) normal (0, 0, 1) x axis (-1, 0, 0)
  line L1 (-23.1826, 2.9542) -> (-16.55, 2.9542)
  line L2 (-23.1826, -11.4458) -> (-23.1826, 2.9542)
  line L3 (-17.255, -11.4458) -> (-23.1826, -11.4458)
  line L4 (0.1537, -10.7673) -> (-3.4928, -7.1208)
  line L5 (0.1537, -18.4744) -> (0.1537, -10.7673)
  line L6 (-3.4928, -22.1208) -> (0.1537, -18.4744)
  line L7 (-23.1826, -17.7958) -> (-17.255, -17.7958)
  line L8 (-23.1826, -27.7521) -> (-23.1826, -17.7958)
  line L9 (-16.8326, -34.1021) -> (-23.1826, -27.7521)
  line L10 (0.0399, -34.1021) -> (-16.8326, -34.1021)
  line L11 (6.3899, -27.7521) -> (0.0399, -34.1021)
  line L12 (6.3899, 19.0104) -> (6.3899, -27.7521)
  line L13 (0.0399, 25.3604) -> (6.3899, 19.0104)
  line L14 (-16.8326, 25.3604) -> (0.0399, 25.3604)
  line L15 (-23.1826, 19.0104) -> (-16.8326, 25.3604)
  line L16 (-23.1826, 9.3042) -> (-23.1826, 19.0104)
  line L17 (-16.55, 9.3042) -> (-23.1826, 9.3042)
  line L18 (6.3899, -27.7521) -> (0.0399, -34.1021)
  line L19 (6.3899, 19.0104) -> (6.3899, -27.7521)
  line L20 (0.0399, 25.3604) -> (6.3899, 19.0104)
  line L21 (-16.8326, 25.3604) -> (0.0399, 25.3604)
  line L22 (-23.1826, 19.0104) -> (-16.8326, 25.3604)
  line L23 (-23.1826, -27.7521) -> (-23.1826, 19.0104)
  line L24 (-16.8326, -34.1021) -> (-23.1826, -27.7521)
  line L25 (0.0399, -34.1021) -> (-16.8326, -34.1021)
  line L26 (0.8337, 14.8742) -> (-17.6263, 14.8742)
  line L27 (0.8337, -23.6158) -> (0.8337, 14.8742)
  line L28 (-17.6263, -23.6158) -> (0.8337, -23.6158)
  line L29 (-17.6263, 14.8742) -> (-17.6263, -23.6158)
  arc A1 centre (-8.3963, 6.1292) radius 8.75 clockwise from (-16.55, 9.3042) to (-16.55, 2.9542)
  arc A2 centre (-9.026, -14.6208) radius 8.8203 clockwise from (-17.255, -11.4458) to (-13.668, -7.1208)
  arc A3 centre (-8.5804, -15.3408) radius 9.6671 clockwise from (-13.668, -7.1208) to (-3.4928, -7.1208)
  arc A4 centre (-8.5804, -13.9008) radius 9.6671 clockwise from (-3.4928, -22.1208) to (-13.668, -22.1208)
  arc A5 centre (-9.026, -14.6208) radius 8.8203 clockwise from (-13.668, -22.1208) to (-17.255, -17.7958)
  circle C1 centre (-3.4963, 20.4292) radius 2.2
  circle C2 centre (-13.2963, 20.4292) radius 2.2
  circle C3 centre (-3.4963, -29.1708) radius 2.2
  circle C4 centre (-13.2963, -29.1708) radius 2.2
extrude "Extrude7" cut sketch "Sketch23" profile of C1 C2 C3 C4 against normal blind 6
delete_face "DeleteFace1"
remove_body "RemoveBody2"
remove_body "RemoveBody3"
remove_body "RemoveBody4"
remove_body "RemoveBody5"
delete_face "DeleteFace1"
delete_face "DeleteFace2"
delete_face "DeleteFace3"
delete_face "DeleteFace4"
position "Position6"
sketch "Sketch24" plane through (0, 0, 28) normal (0, 0, 1) x axis (-1, 0, 0)
  line L1 (6.3899, -27.7521) -> (0.0399, -34.1021)
  line L2 (6.3899, 19.0104) -> (6.3899, -27.7521)
  line L3 (0.0399, 25.3604) -> (6.3899, 19.0104)
  line L4 (-16.8326, 25.3604) -> (0.0399, 25.3604)
  line L5 (-23.1826, 19.0104) -> (-16.8326, 25.3604)
  line L6 (-23.1826, -27.7521) -> (-23.1826, 19.0104)
  line L7 (-16.8326, -34.1021) -> (-23.1826, -27.7521)
  line L8 (0.0399, -34.1021) -> (-16.8326, -34.1021)
  line L9 (0.8337, 14.8742) -> (-17.6263, 14.8742)
  line L10 (0.8337, -23.6158) -> (0.8337, 14.8742)
  line L11 (-17.6263, -23.6158) -> (0.8337, -23.6158)
  line L12 (-17.6263, 14.8742) -> (-17.6263, -23.6158)
  circle C1 centre (-3.4963, -29.1708) radius 1.5
  circle C2 centre (-3.4963, -29.1708) radius 1.5
  concentric C1 C2
  dimension "d205" diameter C2 = 3
extrude "Extrude1" cut sketch "Sketch24" profile of C2 against normal blind 43.18
mirror "Mirror1" mirrorStitchTolerance 0.1016
mirror "Mirror2" mirrorStitchTolerance 0.1016
extrude "Extrude8" cut of existing geometry blind -25.4
sketch "Sketch1" plane through (0, 0, 0) normal (0, 0, 1) x axis (1, 0, 0)
  circle C1 centre (0, 0) radius 2.45
  circle C2 centre (0, 0) radius 1.5
  circle C3 centre (0, 0) radius 1.95
  point P1 (0, 0)
  point P2 (0, 0)
  coincident P1 P2
  concentric C1 C2
  concentric C1 C3
  dimension "d1_3" diameter C1 = 4.9
  dimension "d2_3" diameter C2 = 3
  dimension "d3_3" diameter C3 = 3.9
extrude "Extrude1" new body sketch "Sketch1" distance 0.7 (= "( 1.4 / 2 ) * 1 mm") named "d4_3"
extrude "Extrude2" add sketch "Sketch1" profile of C2 C3 distance 3.3 (= "5 mm - 1.7 mm") named "d6_3"
extrude "Extrude3" of existing geometry blind 1.7 named "d9_3"
extrude "Extrude4" add of existing geometry blind 1.7 named "d11_3"
mirror "Mirror1" mirrorStitchTolerance 0.1 named "d14_2"
extrude "Extrude5" new body sketch "Sketch1" profile of C2 C3 distance 3 named "d15_2"
extrude "Extrude6" sketch "Sketch1" blind -1.8 named "d18_2"
mirror "Mirror2" mirrorStitchTolerance 0.1 named "d21_2"
move "Move1"
remove_body "RemoveBody1"
extrude "Extrude9" cut of existing geometry blind -0.4826 (= "10 mm - 0.4127007874015741 in")
position "Position7"
mirror "Mirror3" mirrorStitchTolerance 0.1016
mirror "Mirror4" mirrorStitchTolerance 0.1016
copy_paste "CutPaste6"
offset_faces "OffsetFaces1" distance -3.175
delete_face "DeleteFace2"
delete_face "DeleteFace3"
delete_face "DeleteFace4"
chamfer "Chamfer1" distance 4.7625
remove_instance "RemoveInstance1"
offset_faces "OffsetFaces2" distance -0.2
sketch "Sketch25" plane through (0, 0, 1.008) normal (0, 0, 1) x axis (-1, 0, 0)
  line L1 (-20.0076, 9.3042) -> (-16.55, 9.3042)
  line L2 (-20.0076, 2.9542) -> (-20.0076, 9.3042)
  line L3 (-16.55, 2.9542) -> (-20.0076, 2.9542)
  line L4 (-20.0076, -11.4458) -> (-17.255, -11.4458)
  line L5 (-20.0076, -17.7958) -> (-20.0076, -11.4458)
  line L6 (-17.255, -17.7958) -> (-20.0076, -17.7958)
  line L7 (-3.4928, -22.1208) -> (-13.668, -22.1208)
  line L8 (0.1537, -18.4744) -> (-3.4928, -22.1208)
  line L9 (0.1537, -10.7673) -> (0.1537, -18.4744)
  line L10 (-3.4928, -7.1208) -> (0.1537, -10.7673)
  line L11 (-13.668, -7.1208) -> (-3.4928, -7.1208)
  line L12 (-20.0076, -17.7958) -> (-17.255, -17.7958)
  line L13 (-20.0076, -11.4458) -> (-20.0076, -17.7958)
  line L14 (-17.255, -11.4458) -> (-20.0076, -11.4458)
  line L15 (-17.255, -17.7958) -> (-17.255, -11.4458)
  line L16 (-20.0076, 2.9542) -> (-16.55, 2.9542)
  line L17 (-20.0076, 9.3042) -> (-20.0076, 2.9542)
  line L18 (-16.55, 9.3042) -> (-20.0076, 9.3042)
  line L19 (-16.55, 2.9542) -> (-16.55, 9.3042)
  arc A1 centre (-8.3963, 6.1292) radius 8.75 clockwise from (-16.55, 9.3042) to (-16.55, 2.9542)
  arc A2 centre (-9.026, -14.6208) radius 8.8203 clockwise from (-17.255, -11.4458) to (-13.668, -7.1208)
  arc A3 centre (-9.026, -14.6208) radius 8.8203 clockwise from (-13.668, -22.1208) to (-17.255, -17.7958)
  point P10 (-20.0076, -11.4458)
  point P20 (-20.0076, -11.4458)
  point P12 (-17.255, -17.7958)
  point P18 (-17.255, -17.7958)
  point P5 (-20.0076, 9.3042)
  point P24 (-20.0076, 9.3042)
  point P2 (-16.55, 2.9542)
  point P22 (-16.55, 2.9542)
  horizontal L12
  vertical L13
  horizontal L14
  vertical L15
  coincident P10 P20
  coincident P12 P18
  horizontal L16
  vertical L17
  horizontal L18
  vertical L19
  coincident P5 P24
  coincident P2 P22
extrude "Extrude10" cut sketch "Sketch25" profile of L1 L2 L3 L16 L17 L18 L19 against normal blind 8.89
extrude "Extrude11" cut sketch "Sketch25" profile of L4 L5 L6 L12 L13 L14 L15 distance 11.43
copy_paste "CutPaste1"
remove_instance "RemoveInstance8"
